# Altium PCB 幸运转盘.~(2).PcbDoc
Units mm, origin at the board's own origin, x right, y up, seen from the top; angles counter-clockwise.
Board outline 152.4 x 101.6 mm, 2 copper layers (Top Layer, Bottom Layer); 22 components, 17 nets, 67 pads, 1 vias.
Unrouted connection lines stored in the file: 1.
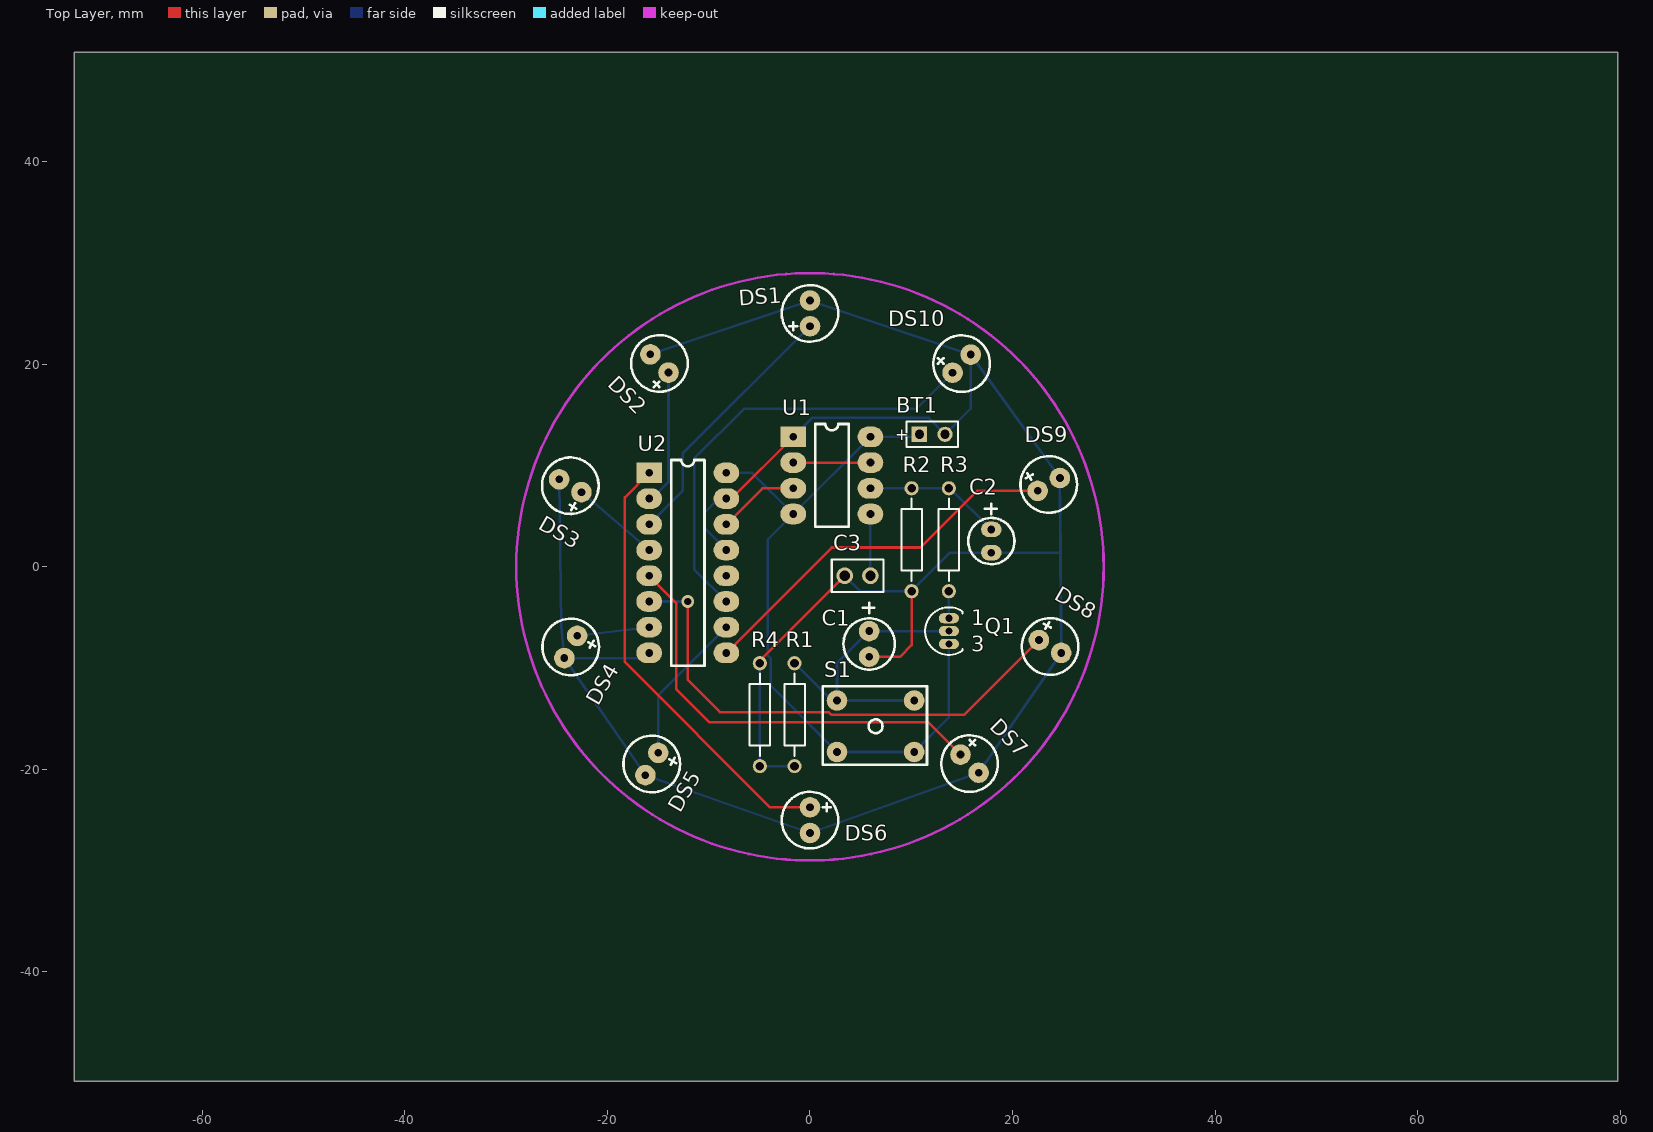
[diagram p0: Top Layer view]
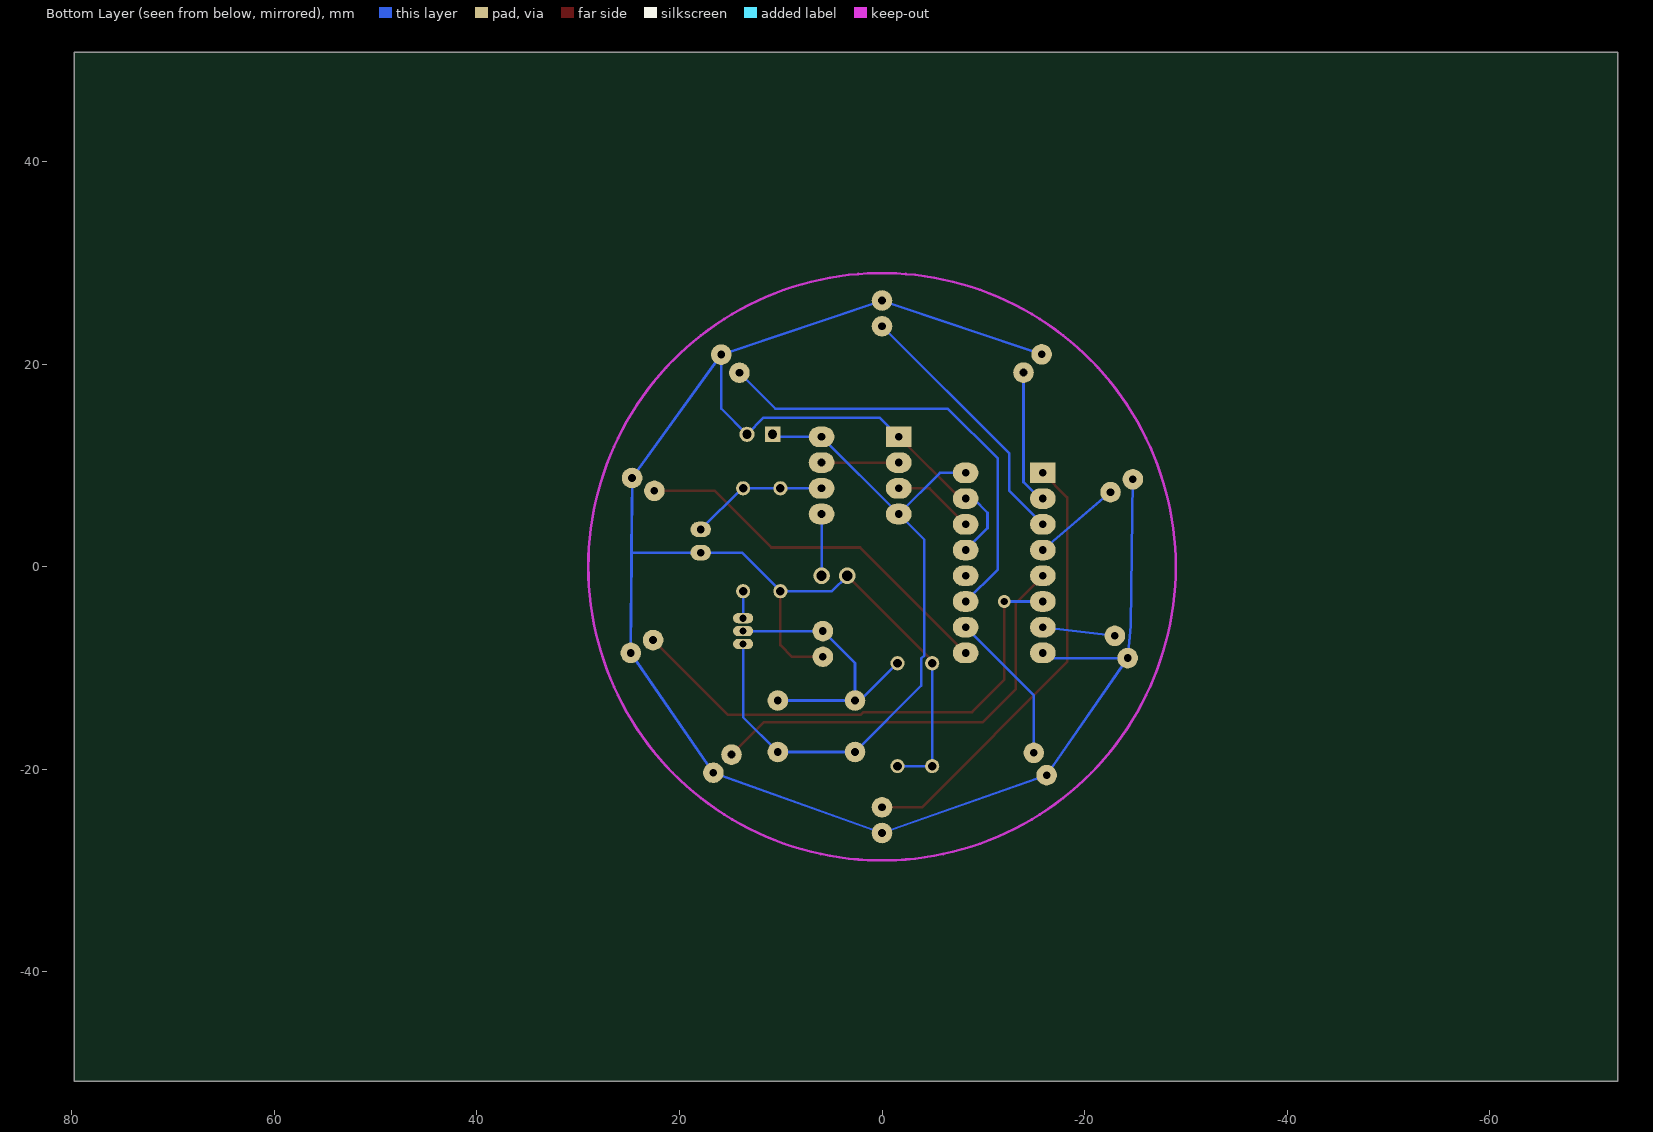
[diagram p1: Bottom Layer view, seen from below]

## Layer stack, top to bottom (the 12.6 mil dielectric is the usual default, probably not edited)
Top Solder: solder mask 0.0102, Solder Resist, Dk 3.5
Top Layer: signal copper 0.0356
Dielectric 1: dielectric 0.32, FR-4, Dk 4.8
Bottom Layer: signal copper 0.0356
Bottom Solder: solder mask 0.0102, Solder Resist, Dk 3.5

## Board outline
-72.644,-50.8 79.756,-50.8 79.756,50.8 -72.644,50.8

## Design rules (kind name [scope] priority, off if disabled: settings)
Clearance [All] p1: gap=0.254
PolygonConnect [All] p1: connectstyle=Relief reliefconductorwidth=0.254 reliefentries=4 polygonreliefangle="90 Angle" airgapwidth=0.254
RoutingVias [All] p1: holewidth=0.711 width=1.27 viastyle="Through Hole" minholewidth=0.711 minwidth=1.27 maxholewidth=0.711 maxwidth=1.27
SolderMaskExpansion [All] p1: expansion=0.102
Width [All] p1: maxlimit=0.254 minlimit=0.254 preferedwidth=0.254
30 further rules are at their usual default settings.

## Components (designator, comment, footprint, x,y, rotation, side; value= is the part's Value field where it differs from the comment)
BT1 "Battery" BAT-2 12.065,13.081 r0 top
C1 "Cap Pol2" 电解电容100uF 5.842,-6.35 r270 top
C2 "Cap Pol2" 电解电容47uF 17.907,3.683 r270 top
C3 "Cap" CAPR2.54-5.1X3.2 4.699,-0.889 r0 top
DS1 "LED1" 发光二极管 0,23.749 r90 top
DS2 "LED0" 发光二极管 -13.97,19.177 r135 top
DS3 "LED1" 发光二极管 -22.565,7.366 r150 top
DS4 "LED2" 发光二极管 -22.987,-6.817 r240 top
DS5 "LED2" 发光二极管 -14.986,-18.374 r240 top
DS6 "LED0" 发光二极管 0,-23.749 r270 top
DS7 "LED2" 发光二极管 14.859,-18.542 r315 top
DS8 "LED1" 发光二极管 22.606,-7.239 r330 top
DS9 "LED1" 发光二极管 22.479,7.493 r30 top
DS10 "LED1" 发光二极管 14.079,19.159 r45 top
Q1 "2N3904" TO-92 13.716,-6.35 r0 top
R1 "Res2" AXIAL-0.4 -1.524,-14.605 r90 top
R2 "Res2" AXIAL-0.4 10.033,2.667 r90 top
R3 "Res2" AXIAL-0.4 13.716,2.667 r270 top
R4 "Res2" AXIAL-0.4 -4.953,-14.605 r270 top
S1 "SW-PB" 轻触开关 2.667,-13.208 r0 top
U1 "NE555N" NE555 -1.651,12.827 r0 top
U2 "CD4017BCN" CD4017 -15.875,9.271 r0 top

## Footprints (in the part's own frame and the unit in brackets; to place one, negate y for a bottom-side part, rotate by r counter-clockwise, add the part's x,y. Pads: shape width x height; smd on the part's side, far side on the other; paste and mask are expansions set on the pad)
AXIAL-0.4 [mm] "Axial Device, Thru-Hole; 2 Leads; 0.4 in Pin Spacing"
  round 1.4 hole 0.85: 1(-5.08,0) 2(5.08,0)
  silkscreen extent -4.06,-1.02 4.06,1.02
BAT-2 [mm] "Battery; 2 Leads"
  rect 1.5x1.5 hole 0.9: 1(-1.27,0)
  round 1.5 hole 0.9: 2(1.27,0)
  silkscreen extent -2.54,-1.27 2.54,1.27
CAPR2.54-5.1X3.2 [mm]
  round 1.65 hole 1: 1(-1.27,0) 2(1.27,0)
  silkscreen extent -2.55,-1.6 2.55,1.6
CD4017 [mil]
  rect 100x80 hole 30: 1(0,0)
  oval 100x80 hole 30: 2(0,-100) 3(0,-200) 4(0,-300) 5(0,-400) 6(0,-500) 7(0,-600) 8(0,-700) 9(300,-700) 10(300,-600) 11(300,-500) 12(300,-400) 13(300,-300) 14(300,-200) 15(300,-100) 16(300,0)
  silkscreen extent 85,-750 215,50
NE555 [mil]
  rect 100x80 hole 30: 1(0,0)
  oval 100x80 hole 30: 2(0,-100) 3(0,-200) 4(0,-300) 5(300,-300) 6(300,-200) 7(300,-100) 8(300,0)
  silkscreen extent 85,-350 215,50
TO-92 [mm] "TO, Flat Index; 3 In-Line, Axial Leads; Body Dia. 4.6mm; Leads 0.41 x 0.39 mm (max)"
  oval 2x1 hole 0.7: 1(0,1.27) 2(0,0) 3(0,-1.27)
  silkscreen extent -2.34,-2.34 1.35,2.34
发光二极管 [mil]
  round 80 hole 30: 1(0,0) 2(100,0)
  silkscreen extent -60,-110 160,110
电解电容47uF [mil]
  oval 60x80 hole 30: 1(0,0) 2(90,0)
  silkscreen extent -100,-90 135,90
电解电容100uF [mil]
  round 80 hole 30: 1(0,0) 2(100,0)
  silkscreen extent -110,-100 150,100
轻触开关 [mil]
  round 80 hole 30: 1(0,0) 1(300,0) 2(0,-200) 2(300,-200)
  silkscreen extent -55,-250 350,55

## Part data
BT1: "Multicell Battery"
C1 C2: "Polarized Capacitor (Axial)"
C3: "Capacitor"
DS1 DS3 DS8 DS9 DS10: "Typical RED GaAs LED"
DS2 DS6: "Typical INFRARED GaAs LED"
DS4 DS5 DS7: "Typical RED, GREEN, YELLOW, AMBER GaAs LED"
Q1: "NPN General Purpose Amplifier"
R1 R2 R3 R4: "Resistor"
S1: "Switch"
U1: "General-Purpose Single Bipolar Timer"
U2: "Decade Counter/Divider with 10 Decoded Outputs"

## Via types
v1: diameter 1.27, hole 0.711, Top Layer to Bottom Layer, 1 vias

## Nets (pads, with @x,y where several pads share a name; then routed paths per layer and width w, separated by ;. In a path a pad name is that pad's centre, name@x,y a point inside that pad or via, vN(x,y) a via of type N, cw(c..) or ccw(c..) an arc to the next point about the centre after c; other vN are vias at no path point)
GND: BT1.2 C1.2 C2.2 C3.1 DS1.2 DS2.2 DS3.2 DS4.2 DS5.2 DS6.2 DS7.2 DS8.2 DS9.2 DS10.2 R1.1 R2.1 R4.1 R4.2 U1.1 U2.8 U2.13 U2.15 | length 256.3
  Top Layer w0.254: U2.15 -7.747,6.731 U1.1 ; R4.1 -4.953,-9.271 C3.1 ; C1.2 8.89,-8.89 10.033,-7.747 R2.1
  Bottom Layer w0.254: DS3.2 -24.544,-5.839 DS4.2 ; U2.8 -16.383,-9.017 DS4.2 ; DS2.2 DS1.2 DS10.2 ; U2.13 -10.414,3.81 -10.414,5.334 -9.017,6.731 U2.15 ; R4.1 R4.2 R1.1 ; U1.1 0.254,14.732 11.684,14.732 BT1.2 15.875,15.621 DS10.2 ; C3.1 4.953,-2.413 R2.1 13.843,1.397 C2.2 24.733,1.397 ; DS4.2 DS5.2 DS6.2 DS7.2 DS8.2 24.733,1.397 ; DS10.2 DS9.2 24.733,1.397
NetBT1_1: BT1.1 Q1.3 S1.2 U1.4 U1.8 U2.16 | length 71.1
  Bottom Layer w0.254: U2.16 -5.715,9.271 U1.4 ; BT1.1 10.541,12.827 U1.8 U1.4 ; Q1.3 13.716,-14.859 10.287,-18.288 2.667,-18.288 -3.872,-11.749 -3.872,-9.077 -4.191,-8.758 -4.191,2.667 U1.4
NetC1_1: C1.1 Q1.2 R1.2 S1.1 | length 29.4
  Bottom Layer w0.254: R1.2 2.159,-13.208 S1.1@2.667,-13.208 ; S1.1@10.287,-13.208 S1.1@2.667,-13.208 ; Q1.2 C1.1 2.667,-9.525 S1.1@2.667,-13.208
NetC2_1: C2.1 R2.2 R3.1 U1.2 U1.6 U1.7 | length 21.2
  Top Layer w0.254: U1.2 U1.7
  Bottom Layer w0.254: U1.6 R2.2 R3.1 13.843,7.747 C2.1
NetC3_2: C3.2 U1.5 | length 6.1
  Bottom Layer w0.254: C3.2 U1.5
NetDS1_1: DS1.1 U2.3 | length 26.1
  Bottom Layer w0.254: U2.3 -12.573,7.493 -12.573,11.176 DS1.1
NetDS2_1: DS2.1 U2.2 | length 13.4
  Bottom Layer w0.254: U2.2 -15.59,6.731 -13.97,8.351 DS2.1
NetDS3_1: DS3.1 U2.4 | length 8.8
  Bottom Layer w0.254: DS3.1 U2.4
NetDS4_1: DS4.1 U2.7 | length 7.2
  Bottom Layer w0.254: DS4.1 U2.7
NetDS5_1: DS5.1 U2.10 | length 15.2
  Bottom Layer w0.254: DS5.1 -14.986,-12.7 U2.10
NetDS6_1: DS6.1 U2.1 | length 43.9
  Top Layer w0.254: U2.1 -18.288,6.858 -18.288,-9.398 -3.937,-23.749 DS6.1
NetDS7_1: DS7.1 U2.5 | length 43
  Top Layer w0.254: U2.5 -13.208,-3.556 -13.208,-12.065 -9.906,-15.367 11.684,-15.367 DS7.1
NetDS8_1: DS8.1 U2.6 | length 50.7
  Top Layer w0.254: v1(-12.065,-3.429) -12.065,-11.176 -8.89,-14.351 1.834,-14.351 2.088,-14.605 15.24,-14.605 DS8.1
  Bottom Layer w0.254: U2.6 v1(-12.065,-3.429)
NetDS9_1: DS9.1 U2.9 | length 37.4
  Top Layer w0.254: U2.9 2.159,1.905 10.922,1.905 16.51,7.493 DS9.1
NetDS10_1: DS10.1 U2.11 | length 44.4
  Bottom Layer w0.254: U2.11 -11.43,-0.254 -11.43,10.668 -6.477,15.621 10.541,15.621 DS10.1
NetQ1_1: Q1.1 R3.2 | length 2.7
  Bottom Layer w0.254: Q1.1 R3.2
NetU1_3: U1.3 U2.14 | length 8.1
  Top Layer w0.254: U2.14 -4.699,7.747 U1.3
pads on no net: U2.12

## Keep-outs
Keep-Out Layer:
  circle w0.254: c0,0 r29

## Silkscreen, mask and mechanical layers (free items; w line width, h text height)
Mechanical 1:
  circle w0.254: c0,0 r30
